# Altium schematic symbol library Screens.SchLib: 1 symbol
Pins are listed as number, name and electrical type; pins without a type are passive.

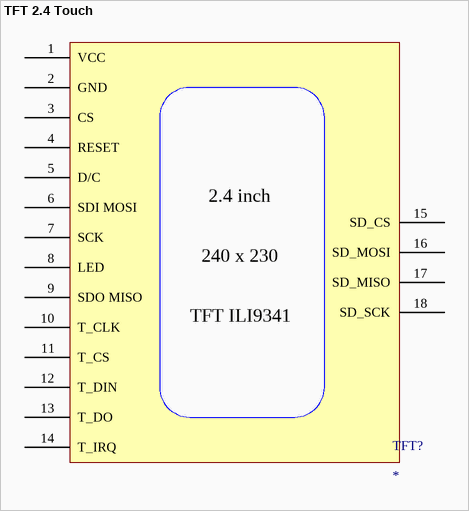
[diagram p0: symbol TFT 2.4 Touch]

## TFT 2.4 Touch
designator TFT?
TFT ILI9341 de 240 x 230 px y 2.4 pulgadas
footprint TFT_2-4_TOUCH
pins: 1 VCC, 2 GND, 3 CS, 4 RESET, 5 D/C, 6 SDI MOSI, 7 SCK, 8 LED, 9 SDO MISO, 10 T_CLK, 11 T_CS, 12 T_DIN, 13 T_DO, 14 T_IRQ, 15 SD_CS, 16 SD_MOSI, 17 SD_MISO, 18 SD_SCK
